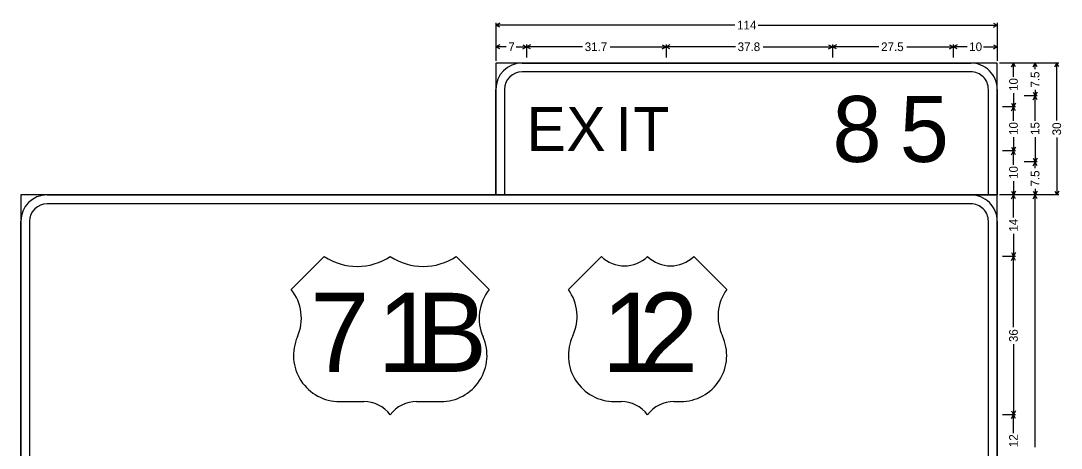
# Model space of a CAD drawing. Extents: x 667331 to 731245, y 738830 to 753817.
# Drawn here: x 728339.6 to 728765.4, y 749858.7 to 750033.6 of the extents above; entities that cross this region are included whole.
import ezdxf

# ---------------------------------------------------------------- set-up
doc = ezdxf.new("R2010")
doc.units = 0
doc.layers.add('R_SIGN', color=7, linetype='Continuous')

msp = doc.modelspace()

# ---------------------------------------------------------------- linework, layer by layer
at = {"layer": 'R_SIGN'}
for p, q in [((728534.04, 750032.73), (728534.04, 750017.23)), ((728535.63, 750032.64), (728534.04, 750031.85)), ((728631.89, 750031.85), (728534.04, 750031.85)), ((728535.63, 750031.05), (728534.04, 750031.85)), ((728641.4, 750031.85), (728739.24, 750031.85)), ((728737.66, 750032.64), (728739.24, 750031.85)), ((728737.66, 750031.05), (728739.24, 750031.85)), ((728739.24, 750032.73), (728739.24, 750017.23)), ((728534.04, 750023.87), (728534.04, 750018.56)), ((728535.63, 750023.78), (728534.04, 750022.99)), ((728538.26, 750022.99), (728534.04, 750022.99)), ((728535.63, 750022.2), (728534.04, 750022.99)), ((728542.43, 750022.99), (728546.64, 750022.99)), ((728545.06, 750023.78), (728546.64, 750022.99)), ((728545.06, 750022.2), (728546.64, 750022.99)), ((728546.64, 750023.87), (728546.64, 750018.56)), ((728548.23, 750023.78), (728546.64, 750022.99)), ((728569.54, 750022.99), (728546.64, 750022.99)), ((728548.23, 750022.2), (728546.64, 750022.99)), ((728580.81, 750022.99), (728603.7, 750022.99)), ((728602.12, 750023.78), (728603.7, 750022.99)), ((728602.12, 750022.2), (728603.7, 750022.99)), ((728603.7, 750023.87), (728603.7, 750018.56)), ((728605.29, 750023.78), (728603.7, 750022.99)), ((728632.12, 750022.99), (728603.7, 750022.99)), ((728605.29, 750022.2), (728603.7, 750022.99)), ((728643.41, 750022.99), (728671.83, 750022.99)), ((728670.25, 750023.78), (728671.83, 750022.99)), ((728670.25, 750022.2), (728671.83, 750022.99)), ((728671.83, 750023.87), (728671.83, 750018.56)), ((728673.42, 750023.78), (728671.83, 750022.99)), ((728690.86, 750022.99), (728671.83, 750022.99)), ((728673.42, 750022.2), (728671.83, 750022.99)), ((728702.22, 750022.99), (728721.24, 750022.99)), ((728719.66, 750023.78), (728721.24, 750022.99)), ((728719.66, 750022.2), (728721.24, 750022.99)), ((728721.24, 750023.87), (728721.24, 750018.56)), ((728721.24, 750023.87), (728721.24, 750018.56)), ((728722.83, 750023.78), (728721.24, 750022.99)), ((728726.9, 750022.99), (728721.24, 750022.99)), ((728722.83, 750022.2), (728721.24, 750022.99)), ((728733.59, 750022.99), (728739.24, 750022.99)), ((728737.66, 750023.78), (728739.24, 750022.99)), ((728737.66, 750022.2), (728739.24, 750022.99)), ((728739.24, 750023.87), (728739.24, 750018.56)), ((728764.49, 750016.34), (728740.13, 750016.34)), ((728746.77, 750016.34), (728741.46, 750016.34)), ((728745.09, 750014.76), (728745.89, 750016.34)), ((728745.89, 750010.69), (728745.89, 750016.34)), ((728746.68, 750014.76), (728745.89, 750016.34)), ((728755.63, 750016.34), (728750.32, 750016.34)), ((728753.95, 750014.76), (728754.74, 750016.34)), ((728754.74, 750013.82), (728754.74, 750016.34)), ((728755.54, 750014.76), (728754.74, 750016.34)), ((728762.81, 750014.76), (728763.6, 750016.34)), ((728763.6, 749992.85), (728763.6, 750016.34)), ((728764.4, 750014.76), (728763.6, 750016.34)), ((728745.89, 750004), (728745.89, 749998.34)), ((728753.95, 750004.43), (728754.74, 750002.84)), ((728754.74, 750005.37), (728754.74, 750002.84)), ((728755.54, 750004.43), (728754.74, 750002.84)), ((728745.09, 749999.93), (728745.89, 749998.34)), ((728746.68, 749999.93), (728745.89, 749998.34)), ((728755.63, 750002.84), (728750.32, 750002.84)), ((728753.95, 750001.26), (728754.74, 750002.84)), ((728754.74, 749992.7), (728754.74, 750002.84)), ((728755.54, 750001.26), (728754.74, 750002.84)), ((728746.77, 749998.34), (728741.46, 749998.34)), ((728745.09, 749996.76), (728745.89, 749998.34)), ((728745.89, 749992.69), (728745.89, 749998.34)), ((728746.68, 749996.76), (728745.89, 749998.34)), ((728745.89, 749986), (728745.89, 749980.34)), ((728754.74, 749985.99), (728754.74, 749975.84)), ((728763.6, 749985.84), (728763.6, 749962.34)), ((728746.77, 749980.34), (728741.46, 749980.34)), ((728746.77, 749980.34), (728741.46, 749980.34)), ((728745.09, 749981.93), (728745.89, 749980.34)), ((728745.09, 749978.76), (728745.89, 749980.34)), ((728746.68, 749981.93), (728745.89, 749980.34)), ((728745.89, 749974.69), (728745.89, 749980.34)), ((728746.68, 749978.76), (728745.89, 749980.34)), ((728755.63, 749975.84), (728750.32, 749975.84)), ((728755.63, 749975.84), (728750.32, 749975.84)), ((728753.95, 749977.43), (728754.74, 749975.84)), ((728753.95, 749974.26), (728754.74, 749975.84)), ((728755.54, 749977.43), (728754.74, 749975.84)), ((728754.74, 749973.32), (728754.74, 749975.84)), ((728755.54, 749974.26), (728754.74, 749975.84)), ((728745.89, 749968), (728745.89, 749962.34)), ((728764.49, 749962.34), (728740.13, 749962.34)), ((728755.63, 749962.34), (728740.13, 749962.34)), ((728746.77, 749962.34), (728741.46, 749962.34)), ((728746.77, 749962.34), (728741.46, 749962.34)), ((728745.09, 749963.93), (728745.89, 749962.34)), ((728745.09, 749960.76), (728745.89, 749962.34)), ((728746.68, 749963.93), (728745.89, 749962.34)), ((728745.89, 749953.08), (728745.89, 749962.34)), ((728746.68, 749960.76), (728745.89, 749962.34)), ((728755.63, 749962.34), (728750.32, 749962.34)), ((728753.95, 749963.93), (728754.74, 749962.34)), ((728753.95, 749960.76), (728754.74, 749962.34)), ((728754.74, 749964.87), (728754.74, 749962.34)), ((728755.54, 749963.93), (728754.74, 749962.34)), ((728754.74, 749859.11), (728754.74, 749962.34)), ((728755.54, 749960.76), (728754.74, 749962.34)), ((728762.81, 749963.93), (728763.6, 749962.34)), ((728764.4, 749963.93), (728763.6, 749962.34)), ((728745.89, 749946.41), (728745.89, 749937.14)), ((728463.84, 749937.14), (728450.34, 749923.64)), ((728531.34, 749923.64), (728517.84, 749937.14)), ((728577.24, 749937.14), (728563.74, 749923.64)), ((728628.54, 749923.64), (728615.04, 749937.14)), ((728746.77, 749937.14), (728741.46, 749937.14)), ((728745.09, 749938.73), (728745.89, 749937.14)), ((728745.09, 749935.56), (728745.89, 749937.14)), ((728746.68, 749938.73), (728745.89, 749937.14)), ((728745.89, 749908.27), (728745.89, 749937.14)), ((728746.68, 749935.56), (728745.89, 749937.14)), ((728745.89, 749901.22), (728745.89, 749872.34)), ((728470.14, 749877.74), (728480.04, 749877.74)), ((728501.64, 749877.74), (728511.54, 749877.74)), ((728582.64, 749877.74), (728585.34, 749877.74)), ((728606.94, 749877.74), (728609.64, 749877.74)), ((728746.77, 749872.34), (728741.46, 749872.34)), ((728745.09, 749873.93), (728745.89, 749872.34)), ((728745.09, 749870.76), (728745.89, 749872.34)), ((728746.68, 749873.93), (728745.89, 749872.34)), ((728745.89, 749864.88), (728745.89, 749872.34)), ((728746.68, 749870.76), (728745.89, 749872.34))]:
    msp.add_line(p, q, dxfattribs=at)
for points in [[(728534.04, 749962.34), (728739.24, 749962.34), (728739.24, 750016.34), (728534.04, 750016.34), (728534.04, 749962.34), (728534.04, 749962.34)], [(728544.84, 750016.34), (728728.44, 750016.34)], [(728728.44, 750012.74), (728544.84, 750012.74)], [(728534.04, 749962.34), (728534.04, 750005.54)], [(728537.64, 750005.54), (728537.64, 749962.34)], [(728735.64, 749962.34), (728735.64, 750005.54)], [(728739.24, 750005.54), (728739.24, 749962.34)], [(728339.64, 749746.34), (728739.24, 749746.34), (728739.24, 749962.34), (728339.64, 749962.34), (728339.64, 749746.34), (728339.64, 749746.34)], [(728350.44, 749962.34), (728728.44, 749962.34)], [(728728.44, 749958.74), (728350.44, 749958.74)], [(728339.64, 749746.34), (728339.64, 749951.54)], [(728343.24, 749951.54), (728343.24, 749746.34)], [(728735.64, 749746.34), (728735.64, 749951.54)], [(728739.24, 749951.54), (728739.24, 749746.34)]]:
    msp.add_lwpolyline(points, dxfattribs=at)
for centre, radius, start, end in [((728544.84, 750005.54), 10.8, 90.0002, 179.9998), ((728728.44, 750005.54), 10.8, 0, 90.0002), ((728544.84, 750005.54), 7.2, 90.0002, 179.9998), ((728728.44, 750005.54), 7.2, 0, 90.0002), ((728350.44, 749951.54), 10.8, 90.0002, 179.9998), ((728728.44, 749951.54), 10.8, 0, 90.0002), ((728350.44, 749951.54), 7.2, 90.0002, 179.9998), ((728728.44, 749951.54), 7.2, 0, 90.0002), ((728477.34, 749957.35), 24.3, 236.2511, 303.749), ((728504.34, 749957.35), 24.3, 236.2511, 303.749), ((728586.69, 749946.79), 13.5, 225.5729, 314.4272), ((728605.59, 749946.79), 13.5, 225.5729, 314.4272), ((728435.55, 749911.88), 18.9, 336.2288, 38.4916), ((728546.14, 749911.88), 18.9, 141.5085, 203.7713), ((728548.39, 749912.63), 18.9, 334.9901, 35.6629), ((728643.9, 749912.63), 18.9, 144.3372, 205.0106), ((728470.14, 749896.64), 18.9, 156.2284, 270.0001), ((728511.54, 749896.64), 18.9, 270.0001, 23.7717), ((728582.64, 749896.64), 18.9, 154.9897, 270.0001), ((728609.64, 749896.64), 18.9, 270.0001, 25.0104), ((728480.04, 749864.24), 13.5, 36.8699, 90.0002), ((728501.64, 749864.24), 13.5, 90.0002, 143.13), ((728585.34, 749864.24), 13.5, 36.8699, 90.0002), ((728606.94, 749864.24), 13.5, 90.0002, 143.13)]:
    msp.add_arc(centre, radius, start, end, dxfattribs=at)

# ---------------------------------------------------------------- texts
for s, height, p in [('114', 3.543, (728632.77, 750030.08)), ('7', 3.54, (728539.15, 750021.22)), ('31.7', 3.543, (728570.42, 750021.22)), ('37.8', 3.543, (728633.01, 750021.22)), ('27.5', 3.543, (728691.74, 750021.22)), ('10', 3.543, (728727.78, 750021.22)), ('8', 27, (728671.83, 749975.84)), ('5', 27, (728699.37, 749975.84)), ('E', 18, (728546.64, 749980.34)), ('X', 18, (728562.91, 749980.34)), ('I', 18, (728582.99, 749980.34)), ('T', 18, (728590.38, 749980.34)), ('2', 32.4, (728592.74, 749889.89)), ('7', 32.4, (728458.12, 749889.89)), ('1', 32.4, (728485.66, 749889.89)), ('B', 32.4, (728501.53, 749889.89)), ('1', 32.4, (728577.51, 749889.89))]:
    msp.add_text(s, height=height, dxfattribs=at).set_placement(p)
for s, p in [('7.5', (728756.52, 750006.26)), ('10', (728747.66, 750004.89)), ('10', (728747.66, 749986.89)), ('15', (728756.52, 749986.88)), ('30', (728765.38, 749986.73)), ('10', (728747.66, 749968.89)), ('7.5', (728756.52, 749965.76)), ('14', (728747.66, 749947.3)), ('36', (728747.66, 749902.1)), ('12', (728747.66, 749859.1))]:
    msp.add_text(s, height=3.543, rotation=90.0002, dxfattribs=at).set_placement(p)

doc.saveas('drawing.dxf')
